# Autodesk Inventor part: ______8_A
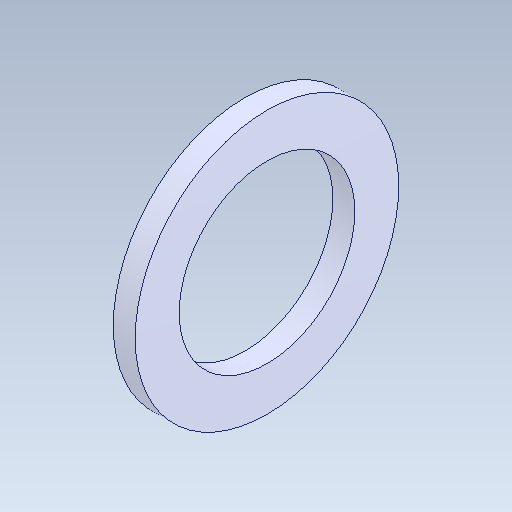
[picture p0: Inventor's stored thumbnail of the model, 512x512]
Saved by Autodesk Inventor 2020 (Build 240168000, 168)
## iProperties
Created: 2017-09
Part Number: ______8_A
Material: Générique
Document SubType Name: Modeling
Designer: bruno
Density: 1 g/cm^3
Appearance: Par défaut
Mass: 0.0628319 g
Surface Area: 1.88496 cm^2
Volume: 0.0628319 cm^3
Sending System: SolidWorks 2016
Author: bruno
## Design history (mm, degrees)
feature "Importée1"
node "Solide1"
